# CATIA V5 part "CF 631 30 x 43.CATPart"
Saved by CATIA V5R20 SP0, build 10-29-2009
Part number: CF 631 30 x 43
Definition: NONE
Nomenclature: CF 631 30 x 43
Source: Unknown
Description: CF 631 30 x 43
Bounding box of the stored display mesh (mm): x -13 to 30, y -26.5 to 26.5, z -26.5 to 26.5
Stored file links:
  C:\Users\Utente\Desktop\IO LAVORO\3D X SITO CF\X SITO\CF 631\CF 631 30 x 43.CATPart
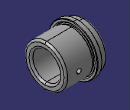
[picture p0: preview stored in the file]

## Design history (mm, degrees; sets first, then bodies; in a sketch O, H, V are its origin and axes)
Body1 "CF 631 30 x 43" (main body)
  Solid1: solid without history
